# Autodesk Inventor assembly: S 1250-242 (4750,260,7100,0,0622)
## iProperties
Category: PARTsolutions
Created: 2011-08
Part Number: S 1250-242 (4750,260,7100,0,0622)
Catalog Web Link: www.cadenas.de
Description: S SX 1250 - Stahlketten
Document SubType Name: Assembly
Designer: PARTsolutions
NB: S 1250-242 (4750,260,7100,0,0622)
NN: S SX 1250
NT: Stahlketten
NBSYN: $TYP.-$BI. ($LK.,$KR.,$LS.,$LV.,$ESP.$STEGV.$FA.$MA.)
LINA: S 1250.242-260-4750 FAI/MAI
PSOL_MULTISOLIDPART: 0.0
TYP: S 1250
BI: 242
BK: 291
BST: 267
LK: 4750
KR: 260
LS: 7100
LV: 0
STEGV: 6
FA: 2
MA: 2
LF: 3737.500
ESP: 0
PSTOL: 0.010
T: 125.000
LS2: 3550.000
DR: 83.186
LB: 1191.814
EASS: 0.000
VAR: 1.000
LKA: 4875.000
MOD1: 1.000
RX2: 520.000
HI: 69
HG: 94
TYP1: S1250
BIMIN: 101.000
BIMAX: 751.000
KRV: 145,200,220,260,300,340,380,420,460,500,540,600,700
LSMAX: 150000.000
BKMIN: 150.000
BKMAX: 800.000
INFO: PDF Katalog
PPATH: assemblies/1250_asmtpl.prj
FABEST: FAI
MABEST: MAI
KT: DUMMY
CreationOption_UseAsmMates: 0
SUPPLIER: Kabelschlepp
ARTICLENO: S 1250-242 (4750,260,7100,0,0622)
BOMINFO: S 1250.242-260-4750 FAI/MAI
CREATOR: CADENAS GmbH
PSOL_IDENT_0: {\\10.0.0.251\ps_data\23d-libs\kabelschlepp\4_eketten_st\s_sx_1250_asmtab.prj},237 {VTYP=3D},{STYP=A
PSOL_IDENT_1: SSTAB},{NB=S 1250-242 (4750,260,7100,0,0622)},{LINA=S 1250.242-260-4750 FAI/MAI},{NN=S SX 1250},{DAT
PSOL_IDENT_2: E=14.01.2010 07:21:25},{GEOMDATE=17.03.2008},{VERSION=},{LINEID=10},{LINESUBID=-1},{WBVAR=BI,KR,LS,L
PSOL_IDENT_3: V,STEGV,FA,MA,ESP}  {NB=S 1250-242 (4750,260,7100,0,0622)},{LINA=S 1250.242-260-4750 FAI/MAI},{KT=DU
PSOL_IDENT_4: MMY},{TYP=S 1250},{BI=242},{BK=291},{BST=267},{LK=4750},{KR=260},{LS=7100},{LV=0},{STEGV=6},{FA=2},{
PSOL_IDENT_5: MA=2},{LF=3737.5},{ESP=0},{PSTOL=0.010},{T=125.000},{LS2=3550},{DR=83.18591},{LB=1191.81409},{EASS=0
PSOL_IDENT_6: },{VAR=1},{LKA=4875},{MOD1=1},{RX2=520},{NB1=},{HI=69},{HG=94},{TYP1=S1250},{BIMIN=101},{BIMAX=751},
PSOL_IDENT_7: {KRV=145,200,220,260,300,340,380,420,460,500,540,600,700},{LSMAX=150000.000},{SV=-100000001504746620
PSOL_IDENT_8: 0000000000000.00},{SV1=},{BKMIN=150},{BKMAX=800},{INFO=PDF Katalog},{PPATH=assemblies/1250_asmtpl.pr
PSOL_IDENT_9: j},{FABEST=FAI},{MABEST=MAI}
Title: S 1250.242-260-4750 FAI/MAI
Author: Cadenas PARTsolutions
Comments: Stahlketten
